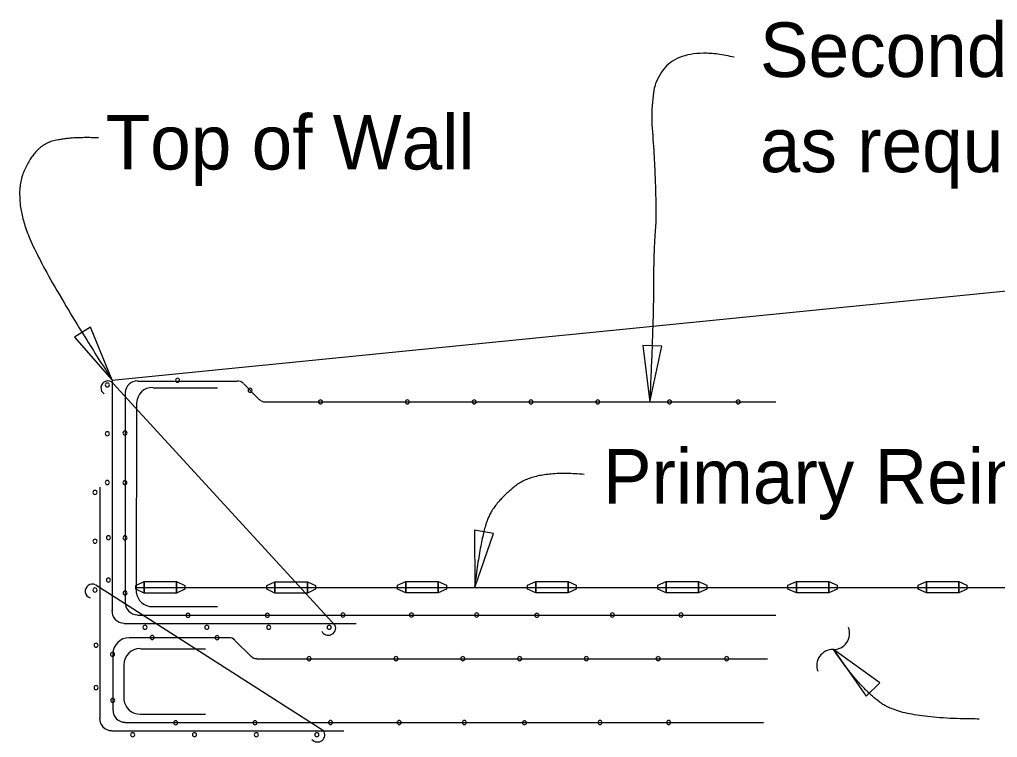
# Model space of a CAD drawing. Extents: x 126777.1 to 126780.68, y 176294.14 to 176295.44.
# Drawn here: x 126779.2289 to 126779.3418, y 176295.2012 to 176295.2841 of the extents above; entities that cross this region are included whole.
import ezdxf

# ---------------------------------------------------------------- set-up
doc = ezdxf.new("R2010")
doc.units = 0
for name, color, linetype in [('AdhocPoint_dp', 7, 'Continuous'), ('Miscellaneous', 7, 'Continuous'), ('Patterning', 7, 'Continuous'), ('SteelMisc_h', 7, 'Continuous'), ('TextMisc', 7, 'Continuous')]:
    doc.layers.add(name, color=color, linetype=linetype)

msp = doc.modelspace()

# ---------------------------------------------------------------- linework, layer by layer
at = {"layer": 'AdhocPoint_dp'}
for p, q in [((126779.23956493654, 176295.24244791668), (126779.42961701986, 176295.26140625)), ((126779.23821076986, 176295.21875), (126779.23815868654, 176295.21875))]:
    msp.add_line(p, q, dxfattribs=at)
for points in [[(126779.23956493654, 176295.24244791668), (126779.23709049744, 176295.2485671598), (126779.23521309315, 176295.2474107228)], [(126779.30164826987, 176295.23989583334), (126779.3030332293, 176295.2463495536), (126779.30083031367, 176295.24644560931)], [(126779.28143993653, 176295.21848958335), (126779.28359160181, 176295.2247296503), (126779.2814162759, 176295.2250901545)], [(126779.32284618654, 176295.21130208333), (126779.32664249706, 176295.20590240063), (126779.32820914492, 176295.20745406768)]]:
    msp.add_lwpolyline(points, close=True, dxfattribs=at)
for centre, radius, start, end in [((126779.32285197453, 176295.21318025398), 0.0018629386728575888, 268.90398055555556, 20.631200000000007), ((126779.3227807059, 176295.20945505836), 0.001862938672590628, 88.90398055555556, 200.63120000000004)]:
    msp.add_arc(centre, radius, start, end, dxfattribs=at)
for points in [[(126779.31140286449, 176295.27974317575), (126779.30129289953, 176295.28208021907), (126779.30250948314, 176295.2626132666), (126779.30207210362, 176295.2573590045), (126779.30207210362, 176295.24918570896), (126779.30163472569, 176295.23993061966)], [(126779.23799579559, 176295.27042020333), (126779.23435264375, 176295.2705660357), (126779.23063662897, 176295.26939937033), (126779.22820493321, 176295.26383686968), (126779.23129239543, 176295.2553264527), (126779.23954254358, 176295.242482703)], [(126779.29406045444, 176295.231534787), (126779.2885024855, 176295.23204686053), (126779.28389522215, 176295.2284623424), (126779.28221320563, 176295.22487782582), (126779.28140876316, 176295.21852436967)], [(126779.33965911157, 176295.20328028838), (126779.33102567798, 176295.20328028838), (126779.32590415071, 176295.20679449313), (126779.32283123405, 176295.21133367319)]]:
    msp.add_open_spline(points, degree=2, dxfattribs=at)
at = {"layer": 'Miscellaneous'}
msp.add_line((126779.24237743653, 176295.21848958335), (126779.3821691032, 176295.21848958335), dxfattribs=at)
for points in [[(126779.2423253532, 176295.2186979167), (126779.2432628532, 176295.21916666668), (126779.2432628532, 176295.21781250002), (126779.2423253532, 176295.21828125)], [(126779.2432628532, 176295.21916666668), (126779.2470128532, 176295.21916666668), (126779.2470128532, 176295.21781250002), (126779.2432628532, 176295.21781250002)], [(126779.2470128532, 176295.21916666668), (126779.24795035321, 176295.2186979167), (126779.24795035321, 176295.21828125), (126779.2470128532, 176295.21781250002)], [(126779.25742951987, 176295.2186979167), (126779.25836701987, 176295.21911458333), (126779.25836701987, 176295.21781250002), (126779.25742951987, 176295.21828125)], [(126779.25836701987, 176295.21911458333), (126779.26211701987, 176295.21911458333), (126779.26211701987, 176295.21781250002), (126779.25836701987, 176295.21781250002)], [(126779.26211701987, 176295.21911458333), (126779.26305451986, 176295.2186979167), (126779.26305451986, 176295.21828125), (126779.26211701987, 176295.21781250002)], [(126779.27253368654, 176295.21875), (126779.27347118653, 176295.21916666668), (126779.27347118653, 176295.21786458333), (126779.27253368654, 176295.21828125)], [(126779.27347118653, 176295.21916666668), (126779.27722118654, 176295.21916666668), (126779.27722118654, 176295.21786458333), (126779.27347118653, 176295.21786458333)], [(126779.27722118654, 176295.21916666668), (126779.27815868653, 176295.21875), (126779.27815868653, 176295.21828125), (126779.27722118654, 176295.21786458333)], [(126779.28753368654, 176295.21875), (126779.28847118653, 176295.21916666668), (126779.28847118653, 176295.21786458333), (126779.28753368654, 176295.21828125)], [(126779.28847118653, 176295.21916666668), (126779.29222118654, 176295.21916666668), (126779.29222118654, 176295.21786458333), (126779.28847118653, 176295.21786458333)], [(126779.29222118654, 176295.21916666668), (126779.29315868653, 176295.21875), (126779.29315868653, 176295.21828125), (126779.29222118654, 176295.21786458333)], [(126779.30258576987, 176295.21875), (126779.30352326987, 176295.21916666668), (126779.30352326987, 176295.21786458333), (126779.30258576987, 176295.21828125)], [(126779.30352326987, 176295.21916666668), (126779.30727326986, 176295.21916666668), (126779.30727326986, 176295.21786458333), (126779.30352326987, 176295.21786458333)], [(126779.30727326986, 176295.21916666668), (126779.30821076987, 176295.21875), (126779.30821076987, 176295.21828125), (126779.30727326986, 176295.21786458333)], [(126779.31758576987, 176295.21875), (126779.3185753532, 176295.21916666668), (126779.3185753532, 176295.21786458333), (126779.31758576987, 176295.21828125)], [(126779.3185753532, 176295.21916666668), (126779.3223253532, 176295.21916666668), (126779.3223253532, 176295.21786458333), (126779.3185753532, 176295.21786458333)], [(126779.3223253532, 176295.21916666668), (126779.3232628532, 176295.21875), (126779.3232628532, 176295.21828125), (126779.3223253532, 176295.21786458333)], [(126779.33263785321, 176295.21875), (126779.3335753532, 176295.21916666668), (126779.3335753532, 176295.21786458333), (126779.33263785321, 176295.21828125)], [(126779.3335753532, 176295.21916666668), (126779.3373253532, 176295.21916666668), (126779.3373253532, 176295.21786458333), (126779.3335753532, 176295.21786458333)], [(126779.3373253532, 176295.21916666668), (126779.3382628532, 176295.21875), (126779.3382628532, 176295.21828125), (126779.3373253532, 176295.21786458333)]]:
    msp.add_lwpolyline(points, close=True, dxfattribs=at)
at = {"layer": 'Patterning'}
for p, q in [((126779.23956493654, 176295.2425), (126779.23956493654, 176295.21578125)), ((126779.2540441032, 176295.24229166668), (126779.2424816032, 176295.24229166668)), ((126779.26534618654, 176295.21406250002), (126779.2396691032, 176295.24208333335)), ((126779.2410753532, 176295.24098958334), (126779.2410753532, 176295.21677083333)), ((126779.25659618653, 176295.24015625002), (126779.25472118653, 176295.24203125)), ((126779.31617951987, 176295.23989583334), (126779.25722118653, 176295.23989583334)), ((126779.23815868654, 176295.23005208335), (126779.23815868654, 176295.20338541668)), ((126779.26399201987, 176295.20192708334), (126779.23768993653, 176295.21875)), ((126779.2424816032, 176295.21526041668), (126779.31617951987, 176295.21526041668)), ((126779.24097118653, 176295.21432291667), (126779.26774201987, 176295.21432291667)), ((126779.2531066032, 176295.21265625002), (126779.2415441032, 176295.21265625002)), ((126779.2556066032, 176295.21052083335), (126779.2537316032, 176295.21234375)), ((126779.2396691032, 176295.21078125), (126779.2396691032, 176295.204375)), ((126779.31524201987, 176295.21020833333), (126779.25628368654, 176295.21020833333)), ((126779.2410753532, 176295.20286458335), (126779.31477326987, 176295.20286458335)), ((126779.23956493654, 176295.20192708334), (126779.26633576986, 176295.20192708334))]:
    msp.add_line(p, q, dxfattribs=at)
for centre, radius, start, end in [((126779.23909257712, 176295.24152702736), 0.0008108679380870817, 46.772822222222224, 237.35298333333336), ((126779.23901805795, 176295.24188008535), 0.0002346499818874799, 0, 180), ((126779.24249629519, 176295.24093370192), 0.0014092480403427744, 90, 176.86310555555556), ((126779.24712325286, 176295.2424165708), 0.0002346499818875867, 0, 180), ((126779.24712325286, 176295.2424165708), 0.0002346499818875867, 180, 0), ((126779.25403355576, 176295.24140345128), 0.0009394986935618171, 45, 90), ((126779.23901805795, 176295.24188008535), 0.0002346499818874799, 180, 0), ((126779.25550235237, 176295.24126330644), 0.00023464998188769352, 0, 180), ((126779.25550235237, 176295.24126330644), 0.00023464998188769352, 180, 0), ((126779.25723340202, 176295.24086090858), 0.0009394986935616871, 225, 270), ((126779.26362503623, 176295.23992140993), 0.00023464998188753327, 0, 180), ((126779.26362503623, 176295.23992140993), 0.00023464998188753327, 180, 0), ((126779.27366282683, 176295.23992140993), 0.00023464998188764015, 0, 180), ((126779.27366282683, 176295.23992140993), 0.00023464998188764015, 180, 0), ((126779.28137096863, 176295.23992140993), 0.0002346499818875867, 0, 180), ((126779.28137096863, 176295.23992140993), 0.0002346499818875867, 180, 0), ((126779.28793229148, 176295.23992140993), 0.00023464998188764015, 0, 180), ((126779.28793229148, 176295.23992140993), 0.00023464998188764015, 180, 0), ((126779.29564043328, 176295.23992140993), 0.0002346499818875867, 0, 180), ((126779.29564043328, 176295.23992140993), 0.0002346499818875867, 180, 0), ((126779.30392096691, 176295.23992140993), 0.00023464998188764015, 0, 180), ((126779.30392096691, 176295.23992140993), 0.00023464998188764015, 180, 0), ((126779.31184270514, 176295.23992140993), 0.00023464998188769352, 0, 180), ((126779.31184270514, 176295.23992140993), 0.00023464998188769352, 180, 0), ((126779.23901805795, 176295.23624309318), 0.00023464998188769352, 0, 180), ((126779.24105582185, 176295.23631991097), 0.00023464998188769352, 0, 180), ((126779.23901805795, 176295.23624309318), 0.00023464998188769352, 180, 0), ((126779.24105582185, 176295.23631991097), 0.00023464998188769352, 180, 0), ((126779.23901805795, 176295.23060610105), 0.0002346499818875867, 0, 180), ((126779.24104503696, 176295.23059445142), 0.0002346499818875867, 0, 180), ((126779.2375912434, 176295.22946132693), 0.00023464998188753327, 0, 180), ((126779.23901805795, 176295.23060610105), 0.0002346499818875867, 180, 0), ((126779.24104503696, 176295.23059445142), 0.0002346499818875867, 180, 0), ((126779.2375912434, 176295.22946132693), 0.00023464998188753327, 180, 0), ((126779.2375912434, 176295.22382433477), 0.00023464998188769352, 0, 180), ((126779.23914672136, 176295.22422672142), 0.00023464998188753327, 0, 180), ((126779.23914672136, 176295.22422672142), 0.00023464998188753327, 180, 0), ((126779.24105551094, 176295.22421197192), 0.00023464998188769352, 0, 180), ((126779.24105551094, 176295.22421197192), 0.00023464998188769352, 180, 0), ((126779.2375912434, 176295.22382433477), 0.00023464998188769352, 180, 0), ((126779.23914672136, 176295.2193321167), 0.00023464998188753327, 0, 180), ((126779.23726982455, 176295.21805330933), 0.0008108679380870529, 61.695838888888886, 252.276), ((126779.2375912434, 176295.2181873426), 0.00023464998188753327, 0, 180), ((126779.23914672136, 176295.2193321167), 0.00023464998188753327, 180, 0), ((126779.2375912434, 176295.2181873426), 0.00023464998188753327, 180, 0), ((126779.24107061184, 176295.21784447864), 0.00023464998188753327, 0, 180), ((126779.24107061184, 176295.21784447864), 0.00023464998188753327, 180, 0), ((126779.24249348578, 176295.21673129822), 0.0014092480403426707, 176.86310555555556, 270), ((126779.24095322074, 176295.21576739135), 0.0014092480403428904, 176.94386666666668, 270), ((126779.24832180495, 176295.21526426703), 0.00023464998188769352, 0, 180), ((126779.24832180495, 176295.21526426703), 0.00023464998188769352, 180, 0), ((126779.25748751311, 176295.21526426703), 0.00023464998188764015, 0, 180), ((126779.25748751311, 176295.21526426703), 0.00023464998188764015, 180, 0), ((126779.26621096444, 176295.21530191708), 0.00023464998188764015, 0, 180), ((126779.26621096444, 176295.21530191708), 0.00023464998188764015, 180, 0), ((126779.2741327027, 176295.21530191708), 0.00023464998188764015, 0, 180), ((126779.2741327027, 176295.21530191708), 0.00023464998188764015, 180, 0), ((126779.28166174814, 176295.21530191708), 0.0002346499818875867, 0, 180), ((126779.28166174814, 176295.21530191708), 0.0002346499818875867, 180, 0), ((126779.28860525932, 176295.21526426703), 0.00023464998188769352, 0, 180), ((126779.28860525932, 176295.21526426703), 0.00023464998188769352, 180, 0), ((126779.29732871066, 176295.21530191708), 0.00023464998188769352, 0, 180), ((126779.29732871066, 176295.21530191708), 0.00023464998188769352, 180, 0), ((126779.30525044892, 176295.21530191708), 0.00023464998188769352, 0, 180), ((126779.30525044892, 176295.21530191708), 0.00023464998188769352, 180, 0), ((126779.24336750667, 176295.2138806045), 0.0002346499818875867, 0, 180), ((126779.24336750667, 176295.2138806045), 0.0002346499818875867, 180, 0), ((126779.25050769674, 176295.2138806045), 0.00023464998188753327, 0, 180), ((126779.25050769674, 176295.2138806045), 0.00023464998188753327, 180, 0), ((126779.2576478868, 176295.2138806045), 0.00023464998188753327, 0, 180), ((126779.2576478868, 176295.2138806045), 0.00023464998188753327, 180, 0), ((126779.26454239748, 176295.21380206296), 0.0008425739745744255, 205.95775833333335, 20.726922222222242), ((126779.26462775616, 176295.213884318), 0.0002346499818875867, 0, 180), ((126779.26462775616, 176295.213884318), 0.0002346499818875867, 180, 0), ((126779.24419028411, 176295.21270106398), 0.00023464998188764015, 0, 180), ((126779.25169113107, 176295.21267811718), 0.0002346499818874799, 0, 180), ((126779.23771990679, 176295.211807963), 0.00023464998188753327, 0, 180), ((126779.23771990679, 176295.211807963), 0.00023464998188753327, 180, 0), ((126779.24153927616, 176295.2107991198), 0.0018789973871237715, 90, 179.99335000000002), ((126779.24419028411, 176295.21270106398), 0.00023464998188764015, 180, 0), ((126779.25169113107, 176295.21267811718), 0.0002346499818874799, 180, 0), ((126779.2530765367, 176295.2117386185), 0.0009394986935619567, 45, 90), ((126779.2396101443, 176295.21075362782), 0.00023464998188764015, 0, 180), ((126779.2396101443, 176295.21075362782), 0.00023464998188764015, 180, 0), ((126779.25627638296, 176295.2111960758), 0.0009394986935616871, 225, 270), ((126779.2623121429, 176295.21025657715), 0.00023464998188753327, 0, 180), ((126779.27234993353, 176295.21025657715), 0.00023464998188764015, 0, 180), ((126779.28005807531, 176295.21025657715), 0.0002346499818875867, 0, 180), ((126779.28661939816, 176295.21025657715), 0.00023464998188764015, 0, 180), ((126779.29432753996, 176295.21025657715), 0.0002346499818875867, 0, 180), ((126779.30260807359, 176295.21025657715), 0.00023464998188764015, 0, 180), ((126779.31052981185, 176295.21025657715), 0.00023464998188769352, 0, 180), ((126779.2623121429, 176295.21025657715), 0.00023464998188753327, 180, 0), ((126779.27234993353, 176295.21025657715), 0.00023464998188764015, 180, 0), ((126779.28005807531, 176295.21025657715), 0.0002346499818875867, 180, 0), ((126779.28661939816, 176295.21025657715), 0.00023464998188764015, 180, 0), ((126779.29432753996, 176295.21025657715), 0.0002346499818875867, 180, 0), ((126779.30260807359, 176295.21025657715), 0.00023464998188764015, 180, 0), ((126779.31052981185, 176295.21025657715), 0.00023464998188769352, 180, 0), ((126779.23771990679, 176295.2069133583), 0.00023464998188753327, 0, 180), ((126779.23771990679, 176295.2069133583), 0.00023464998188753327, 180, 0), ((126779.23964379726, 176295.20542572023), 0.00023464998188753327, 0, 180), ((126779.23964379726, 176295.20542572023), 0.00023464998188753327, 180, 0), ((126779.24106667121, 176295.2043125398), 0.0014092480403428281, 176.86310555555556, 270), ((126779.23952640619, 176295.20334863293), 0.0014092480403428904, 176.94386666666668, 270), ((126779.24689499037, 176295.2028455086), 0.00023464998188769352, 0, 180), ((126779.24689499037, 176295.2028455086), 0.00023464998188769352, 180, 0), ((126779.25606069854, 176295.2028455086), 0.00023464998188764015, 0, 180), ((126779.25606069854, 176295.2028455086), 0.00023464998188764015, 180, 0), ((126779.26478414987, 176295.20288315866), 0.00023464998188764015, 0, 180), ((126779.26478414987, 176295.20288315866), 0.00023464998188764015, 180, 0), ((126779.27270588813, 176295.20288315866), 0.00023464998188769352, 0, 180), ((126779.27270588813, 176295.20288315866), 0.00023464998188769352, 180, 0), ((126779.28023493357, 176295.20288315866), 0.00023464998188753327, 0, 180), ((126779.28023493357, 176295.20288315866), 0.00023464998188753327, 180, 0), ((126779.28717844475, 176295.2028455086), 0.00023464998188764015, 0, 180), ((126779.28717844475, 176295.2028455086), 0.00023464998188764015, 180, 0), ((126779.29590189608, 176295.20288315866), 0.00023464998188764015, 0, 180), ((126779.29590189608, 176295.20288315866), 0.00023464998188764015, 180, 0), ((126779.30382363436, 176295.20288315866), 0.00023464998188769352, 0, 180), ((126779.30382363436, 176295.20288315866), 0.00023464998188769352, 180, 0), ((126779.2419406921, 176295.20146184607), 0.0002346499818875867, 0, 180), ((126779.2419406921, 176295.20146184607), 0.0002346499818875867, 180, 0), ((126779.24908088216, 176295.20146184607), 0.00023464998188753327, 0, 180), ((126779.24908088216, 176295.20146184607), 0.00023464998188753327, 180, 0), ((126779.25622107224, 176295.20146184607), 0.00023464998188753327, 0, 180), ((126779.25622107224, 176295.20146184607), 0.00023464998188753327, 180, 0), ((126779.26328256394, 176295.20146976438), 0.0008425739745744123, 220.8807777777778, 35.64994166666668), ((126779.26320094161, 176295.2014655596), 0.00023464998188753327, 0, 180), ((126779.26320094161, 176295.2014655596), 0.00023464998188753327, 180, 0)]:
    msp.add_arc(centre, radius, start, end, dxfattribs=at)
at = {"layer": 'SteelMisc_h'}
for p, q in [((126779.24430451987, 176295.2415625), (126779.25175243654, 176295.2415625)), ((126779.24237743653, 176295.21791666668), (126779.24242951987, 176295.23979166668)), ((126779.25175243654, 176295.21625), (126779.24425243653, 176295.21625)), ((126779.24284618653, 176295.21140625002), (126779.25034618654, 176295.21140625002)), ((126779.24097118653, 176295.20546875), (126779.24097118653, 176295.20953125)), ((126779.25034618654, 176295.20380208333), (126779.24279410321, 176295.20380208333))]:
    msp.add_line(p, q, dxfattribs=at)
for centre, radius, start, end in [((126779.2442639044, 176295.2397177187), 0.0018789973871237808, 90, 176.86310555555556), ((126779.24422930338, 176295.21814054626), 0.0018789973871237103, 186.41944166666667, 270), ((126779.24281900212, 176295.2095513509), 0.001878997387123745, 89.99999999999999, 179.93290277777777), ((126779.24280248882, 176295.20572178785), 0.0018789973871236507, 186.41944166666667, 270)]:
    msp.add_arc(centre, radius, start, end, dxfattribs=at)

# ---------------------------------------------------------------- texts
at = {"layer": 'TextMisc'}
for s, p in [('Secondary Reinforcement', (126779.31435660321, 176295.27745835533)), ('Top of Wall', (126779.23881844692, 176295.26677083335)), ('as required', (126779.31435660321, 176295.26645833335)), ('Primary Reinforcement', (126779.2962316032, 176295.22817708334))]:
    msp.add_text(s, height=0.0063000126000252, dxfattribs=at).set_placement(p)

doc.saveas('drawing.dxf')
